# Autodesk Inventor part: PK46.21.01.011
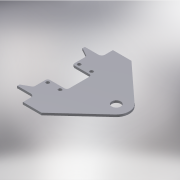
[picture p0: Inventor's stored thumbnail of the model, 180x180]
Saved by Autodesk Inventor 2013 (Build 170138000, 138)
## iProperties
Created: 2005-04
Part Number: PK46.21.01.011
Material: Steel, Mild
Document SubType Name: Modeling
Designer: salex
Manufacturer: Standard
Standards Organization: Custom
Density: 7.86 g/cm^3
Author: salex
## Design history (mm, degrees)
sketch "Эскиз1"
  geometry: L1 (77.853, 84.64)-(-265, 400); L2 (-265, 400)-(-430, 400); L3 (-430, 400)-(-430, 330); L4 (-460, 300)-(-580, 300); L5 (-500, 235)-(-500, 110); L6 (-500, 110)-(-350, 110); L7 (-330, 90)-(-330, -90); L8 (0, 0)-(-389.201, 0); L9 (77.853, -84.64)-(-265, -400); L10 (-265, -400)-(-430, -400); L11 (-500, -110)-(-350, -110); L12 (-430, -400)-(-430, -330); L13 (-460, -300)-(-580, -300); L14 (-500, -235)-(-500, -110); L15 (-580, -300)-(-580, -280); L16 (-580, -280)-(-500, -235); L17 (-580, 300)-(-580, 280); L18 (-580, 280)-(-500, 235); L19 (-500, 235)-(-500, 110); C1 r 40 at (0, 0); C2 r 15 at (-470, -140); C3 r 15 at (-360, -140); C4 r 15 at (-360, 140); C5 r 15 at (-470, 140); A1 r 115 centre (0, 0) between (77.853, -84.64) and (77.853, 84.64); A2 r 30 centre (-460, 330) between (-460, 300) and (-430, 330); A3 r 20 centre (-350, 90) between (-330, 90) and (-350, 110); A4 r 20 centre (-350, -90) between (-350, -110) and (-330, -90); A5 r 30 centre (-460, -330) between (-430, -330) and (-460, -300)
  constraints: 38 end point, 14 symmetric about line, 10 centre point, 10 point on circle, 7 perpendicular, 5 tangent, 3 equal radius, 1 coincident, 1 horizontal, 3 other
  dimensions: "d0" = 30 radius of A2; "d1" = 20 radius of A3; "d2" = 220 diameter of L6 L8; "d3" = 800 diameter of L2 L8; "d5" = 80 diameter of C1; "d6" = 330 distance from line of L7 C1.centre; "d7" = 500 distance from line of L5 C1.centre; "d9" = 100 distance between parallel lines of L2 L4; "d10" = 265 horizontal distance of L1.end C1.centre; "d11" = 115 radius of A1; "d27" = 0 vertical distance of C2.centre C3.centre; "d28" = 0 vertical distance of C4.centre C5.centre; "d29" = 0 horizontal distance of C5.centre C2.centre; "d30" = 0 horizontal distance of C3.centre C4.centre; "d31" = 280 distance of C4.centre C3.centre; "d32" = 280 diameter of C3.centre L8 (= d31); "d33" = 30 diameter of C3; "d34" = 360 horizontal distance of C3.centre C1.centre; "d35" = 110 distance of C2.centre C3.centre; "d36" = 120 distance from line of L17.end L2; "d37" = 470 diameter of L5.start L8; "d38" = 580 distance from line of C1.centre L17; "d39" = 430 distance from line of L12 C1.centre
extrude "Выдавливание1" new body sketch "Эскиз1" distance "d12" = 20; taper "d13" = 0 deg
fillet "Сопряжение1" dims "d40" = 20
body "Solid1"
